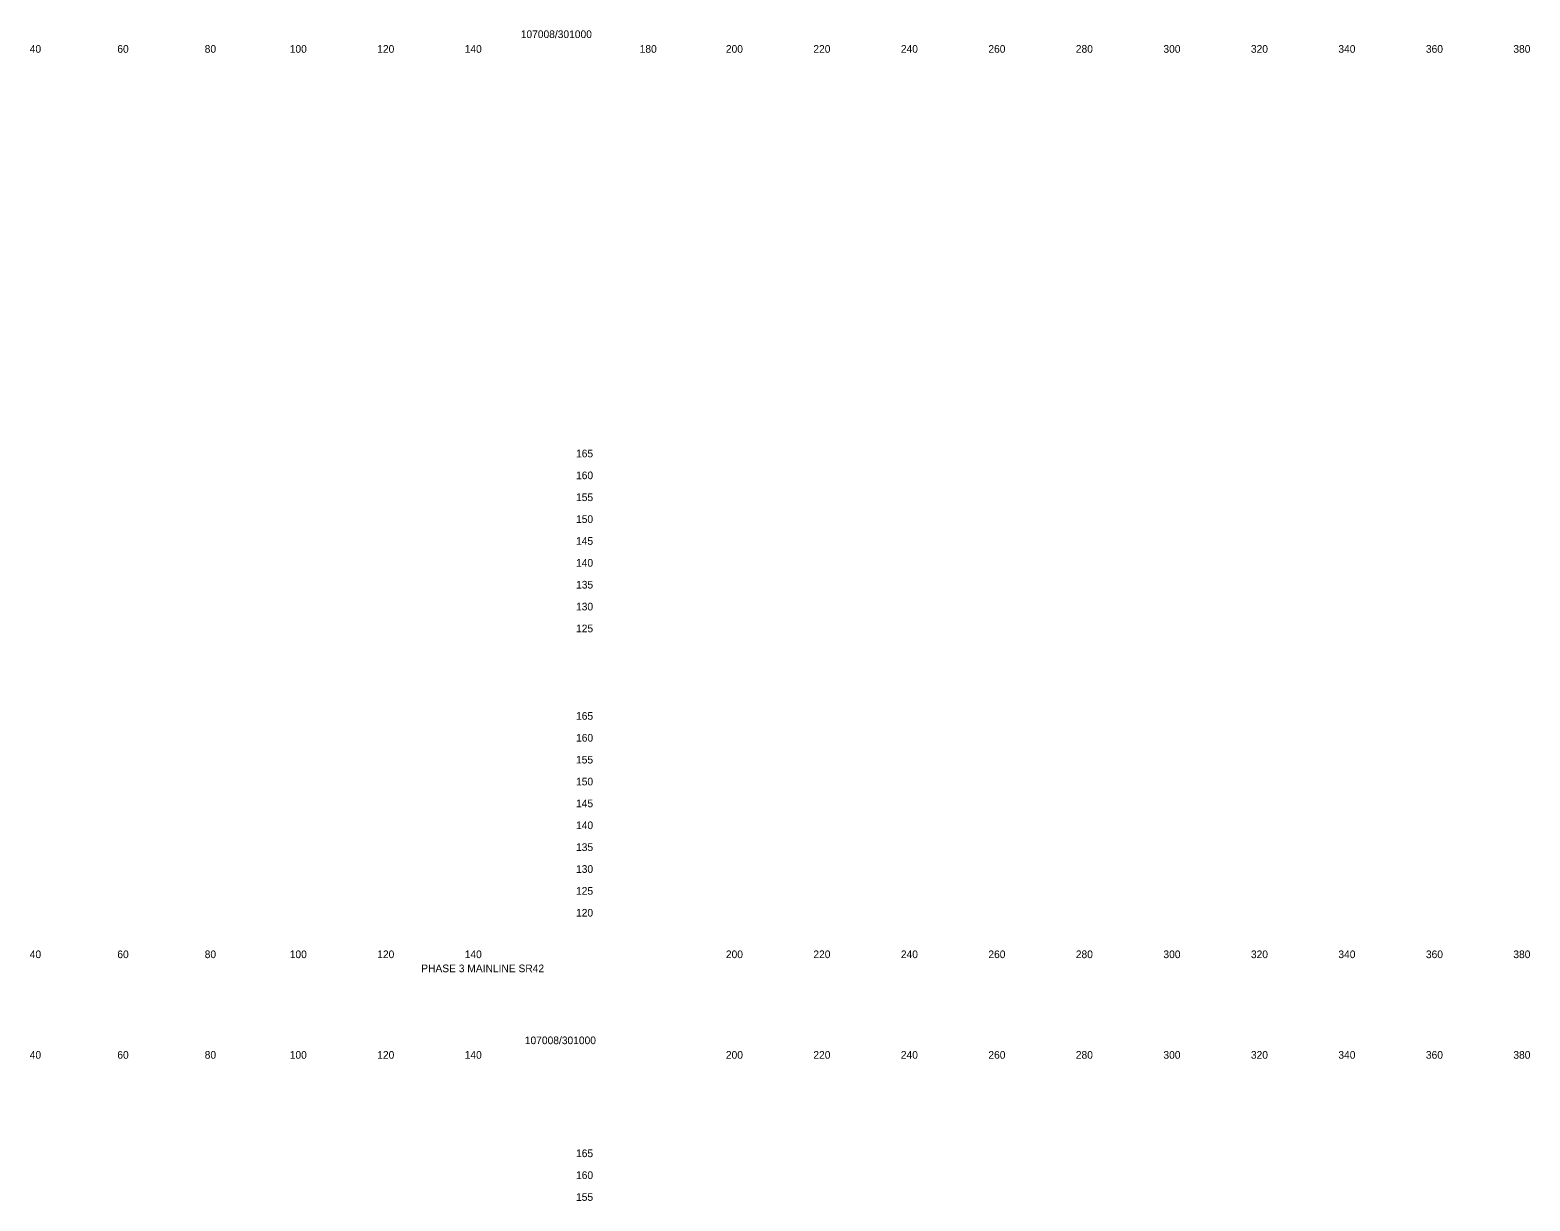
# Model space of a CAD drawing. Extents: x 21281 to 22024, y 6472 to 15198.
# Drawn here: x 21681.3 to 22024.2, y 14929.8 to 15197.5 of the extents above; entities that cross this region are included whole.
import ezdxf

# ---------------------------------------------------------------- set-up
doc = ezdxf.new("R2010")
doc.units = 0
doc.layers.add('Draft_XS_Grid', color=7, linetype='Continuous')
doc.layers.add('Draft_XS_Text', color=7, linetype='Continuous')

msp = doc.modelspace()

# ---------------------------------------------------------------- texts
at = {"layer": 'Draft_XS_Grid'}
for s, p in [('  165  ', (21804.84, 15099.84)), ('  160  ', (21804.84, 15094.84)), ('  155  ', (21804.84, 15089.84)), ('  150  ', (21804.84, 15084.84)), ('  145  ', (21804.84, 15079.84)), ('  140  ', (21804.84, 15074.84)), ('  135  ', (21804.84, 15069.84)), ('  130  ', (21804.84, 15064.84)), ('  125  ', (21804.84, 15059.84)), ('  165  ', (21804.84, 15039.84)), ('  160  ', (21804.84, 15034.84)), ('  155  ', (21804.84, 15029.84)), ('  150  ', (21804.84, 15024.84)), ('  145  ', (21804.84, 15019.84)), ('  140  ', (21804.84, 15014.84)), ('  135  ', (21804.84, 15009.84)), ('  130  ', (21804.84, 15004.84)), ('  125  ', (21804.84, 14999.84)), ('  120  ', (21804.84, 14994.84)), ('  165  ', (21804.84, 14939.84)), ('  160  ', (21804.84, 14934.84)), ('  155  ', (21804.84, 14929.84))]:
    msp.add_text(s, height=1.75, dxfattribs=at).set_placement(p)
at = {"layer": 'Draft_XS_Text'}
for s, p in [('107008/301000', (21793.5, 15195.7)), ('  40  ', (21679.95, 15192.34)), ('  60  ', (21699.97, 15192.34)), ('  80  ', (21719.95, 15192.34)), ('  100  ', (21739.39, 15192.34)), ('  120  ', (21759.39, 15192.34)), ('  140  ', (21779.39, 15192.34)), ('  180  ', (21819.39, 15192.34)), ('  200  ', (21839.1, 15192.34)), ('  220  ', (21859.1, 15192.34)), ('  240  ', (21879.1, 15192.34)), ('  260  ', (21899.11, 15192.34)), ('  280  ', (21919.1, 15192.34)), ('  300  ', (21939.13, 15192.34)), ('  320  ', (21959.13, 15192.34)), ('  340  ', (21979.13, 15192.34)), ('  360  ', (21999.14, 15192.34)), ('  380  ', (22019.13, 15192.34)), ('  40  ', (21679.95, 14985.34)), ('  60  ', (21699.97, 14985.34)), ('  80  ', (21719.95, 14985.34)), ('  100  ', (21739.39, 14985.34)), ('  120  ', (21759.39, 14985.34)), ('  140  ', (21779.39, 14985.34)), ('  200  ', (21839.1, 14985.34)), ('  220  ', (21859.1, 14985.34)), ('  240  ', (21879.1, 14985.34)), ('  260  ', (21899.11, 14985.34)), ('  280  ', (21919.1, 14985.34)), ('  300  ', (21939.13, 14985.34)), ('  320  ', (21959.13, 14985.34)), ('  340  ', (21979.13, 14985.34)), ('  360  ', (21999.14, 14985.34)), ('  380  ', (22019.13, 14985.34)), ('PHASE 3 MAINLINE SR42', (21770.75, 14982.12)), ('107008/301000', (21794.43, 14965.67)), ('  40  ', (21679.95, 14962.34)), ('  60  ', (21699.97, 14962.34)), ('  80  ', (21719.95, 14962.34)), ('  100  ', (21739.39, 14962.34)), ('  120  ', (21759.39, 14962.34)), ('  140  ', (21779.39, 14962.34)), ('  200  ', (21839.1, 14962.34)), ('  220  ', (21859.1, 14962.34)), ('  240  ', (21879.1, 14962.34)), ('  260  ', (21899.11, 14962.34)), ('  280  ', (21919.1, 14962.34)), ('  300  ', (21939.13, 14962.34)), ('  320  ', (21959.13, 14962.34)), ('  340  ', (21979.13, 14962.34)), ('  360  ', (21999.14, 14962.34)), ('  380  ', (22019.13, 14962.34))]:
    msp.add_text(s, height=1.75, dxfattribs=at).set_placement(p)

doc.saveas('drawing.dxf')
